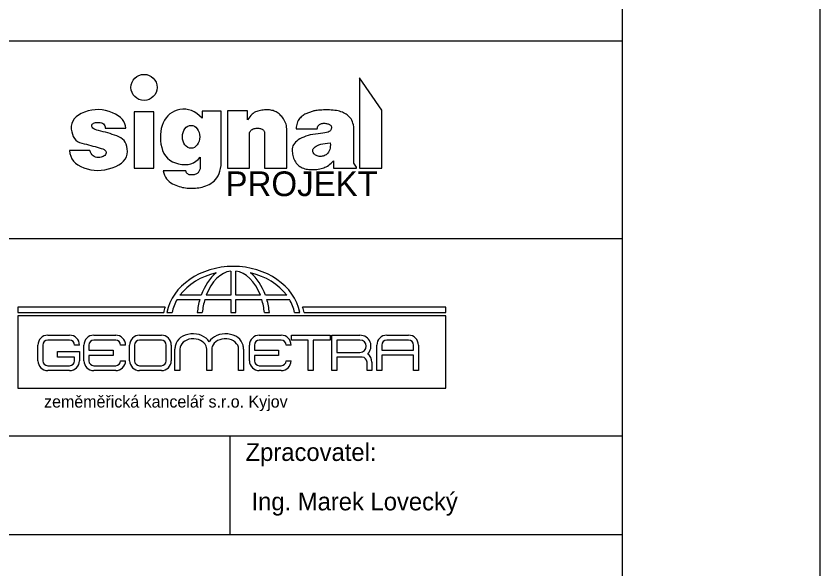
# Model space of a CAD drawing. Extents: x -558358 to -557517, y -1073786 to -1073189.
# Drawn here: x -557597.9 to -557516.5, y -1073685.5 to -1073629.6 of the extents above; entities that cross this region are included whole.
import ezdxf

# ---------------------------------------------------------------- set-up
doc = ezdxf.new("R2010")
doc.units = 0
for name, color, linetype in [('ROZPISKA', 7, 'Continuous'), ('Rozpiska_pole_1', 7, 'Continuous'), ('Rozpiska_pole_6', 7, 'Continuous'), ('Vrstva 1', 7, 'Continuous'), ('ZZZ - Razítko', 7, 'Continuous')]:
    doc.layers.add(name, color=color, linetype=linetype)

msp = doc.modelspace()

# ---------------------------------------------------------------- linework, layer by layer
at = {"layer": 'ROZPISKA'}
for points in [[(-557560.869, -1073644.967), (-557560.869, -1073639.127), (-557563.109, -1073635.847), (-557563.109, -1073644.967), (-557560.869, -1073644.967)], [(-557589.598, -1073645.202), (-557589.236, -1073645.186), (-557588.869, -1073645.138), (-557588.498, -1073645.059), (-557588.122, -1073644.948), (-557587.768, -1073644.812), (-557587.46, -1073644.656), (-557587.199, -1073644.48), (-557586.985, -1073644.284), (-557586.817, -1073644.068), (-557586.697, -1073643.832), (-557586.623, -1073643.576), (-557586.597, -1073643.301), (-557586.607, -1073643.027), (-557586.646, -1073642.778), (-557586.712, -1073642.554), (-557586.806, -1073642.355), (-557586.927, -1073642.18), (-557587.076, -1073642.03), (-557587.253, -1073641.904), (-557587.458, -1073641.804), (-557587.677, -1073641.718), (-557587.899, -1073641.636), (-557588.123, -1073641.558), (-557588.35, -1073641.486), (-557588.579, -1073641.417), (-557588.81, -1073641.353), (-557589.043, -1073641.293), (-557589.279, -1073641.238), (-557589.501, -1073641.183), (-557589.692, -1073641.124), (-557589.852, -1073641.061), (-557589.983, -1073640.994), (-557590.083, -1073640.922), (-557590.152, -1073640.847), (-557590.191, -1073640.768), (-557590.2, -1073640.685), (-557590.183, -1073640.605), (-557590.147, -1073640.537), (-557590.091, -1073640.479), (-557590.015, -1073640.431), (-557589.919, -1073640.395), (-557589.803, -1073640.37), (-557589.668, -1073640.355), (-557589.512, -1073640.351), (-557589.357, -1073640.362), (-557589.222, -1073640.391), (-557589.107, -1073640.439), (-557589.012, -1073640.504), (-557588.937, -1073640.588), (-557588.883, -1073640.69), (-557588.848, -1073640.811), (-557588.834, -1073640.949), (-557586.755, -1073640.949), (-557586.774, -1073640.708), (-557586.836, -1073640.478), (-557586.941, -1073640.261), (-557587.089, -1073640.057), (-557587.28, -1073639.865), (-557587.514, -1073639.686), (-557587.79, -1073639.52), (-557588.11, -1073639.367), (-557588.452, -1073639.237), (-557588.797, -1073639.143), (-557589.145, -1073639.083), (-557589.495, -1073639.058), (-557589.848, -1073639.068), (-557590.203, -1073639.113), (-557590.562, -1073639.193), (-557590.922, -1073639.307), (-557591.26, -1073639.45), (-557591.55, -1073639.612), (-557591.79, -1073639.796), (-557591.983, -1073640), (-557592.126, -1073640.224), (-557592.221, -1073640.469), (-557592.267, -1073640.734), (-557592.265, -1073641.02), (-557592.225, -1073641.302), (-557592.159, -1073641.554), (-557592.067, -1073641.776), (-557591.948, -1073641.969), (-557591.804, -1073642.132), (-557591.633, -1073642.266), (-557591.436, -1073642.37), (-557591.212, -1073642.445), (-557590.977, -1073642.505), (-557590.746, -1073642.565), (-557590.519, -1073642.624), (-557590.295, -1073642.683), (-557590.074, -1073642.741), (-557589.858, -1073642.8), (-557589.645, -1073642.858), (-557589.435, -1073642.916), (-557589.243, -1073642.976), (-557589.081, -1073643.04), (-557588.951, -1073643.109), (-557588.851, -1073643.182), (-557588.783, -1073643.26), (-557588.745, -1073643.343), (-557588.738, -1073643.429), (-557588.762, -1073643.521), (-557588.808, -1073643.609), (-557588.869, -1073643.685), (-557588.945, -1073643.75), (-557589.035, -1073643.803), (-557589.139, -1073643.844), (-557589.257, -1073643.874), (-557589.39, -1073643.893), (-557589.537, -1073643.899), (-557589.686, -1073643.889), (-557589.822, -1073643.856), (-557589.945, -1073643.8), (-557590.056, -1073643.722), (-557590.155, -1073643.62), (-557590.242, -1073643.497), (-557590.316, -1073643.35), (-557590.377, -1073643.182), (-557592.458, -1073643.182), (-557592.414, -1073643.488), (-557592.33, -1073643.771), (-557592.207, -1073644.028), (-557592.045, -1073644.262), (-557591.842, -1073644.472), (-557591.601, -1073644.657), (-557591.319, -1073644.818), (-557590.998, -1073644.954), (-557590.655, -1073645.063), (-557590.307, -1073645.141), (-557589.955, -1073645.187), (-557589.598, -1073645.202)], [(-557583.909, -1073644.967), (-557583.909, -1073639.287), (-557585.909, -1073639.287), (-557585.909, -1073644.967), (-557583.909, -1073644.967)], [(-557580.05, -1073647.009), (-557579.881, -1073647.006), (-557579.711, -1073646.997), (-557579.539, -1073646.984), (-557579.366, -1073646.965), (-557579.192, -1073646.939), (-557579.018, -1073646.9), (-557578.844, -1073646.848), (-557578.67, -1073646.785), (-557578.497, -1073646.71), (-557578.324, -1073646.622), (-557578.152, -1073646.522), (-557577.98, -1073646.41), (-557577.815, -1073646.281), (-557577.667, -1073646.128), (-557577.534, -1073645.952), (-557577.418, -1073645.753), (-557577.317, -1073645.531), (-557577.232, -1073645.286), (-557577.163, -1073645.018), (-557577.109, -1073644.727), (-557577.109, -1073639.207), (-557579.029, -1073639.207), (-557579.029, -1073639.927), (-557579.295, -1073639.673), (-557579.566, -1073639.46), (-557579.84, -1073639.288), (-557580.119, -1073639.157), (-557580.402, -1073639.067), (-557580.69, -1073639.018), (-557580.981, -1073639.01), (-557581.277, -1073639.044), (-557581.564, -1073639.112), (-557581.83, -1073639.209), (-557582.073, -1073639.334), (-557582.295, -1073639.488), (-557582.495, -1073639.67), (-557582.673, -1073639.881), (-557582.83, -1073640.121), (-557582.965, -1073640.388), (-557583.075, -1073640.674), (-557583.16, -1073640.967), (-557583.219, -1073641.267), (-557583.252, -1073641.575), (-557583.259, -1073641.889), (-557583.24, -1073642.211), (-557583.196, -1073642.54), (-557583.125, -1073642.876), (-557583.025, -1073643.199), (-557582.892, -1073643.49), (-557582.727, -1073643.748), (-557582.529, -1073643.974), (-557582.298, -1073644.166), (-557582.035, -1073644.326), (-557581.738, -1073644.454), (-557581.41, -1073644.548), (-557581.073, -1073644.606), (-557580.755, -1073644.624), (-557580.454, -1073644.6), (-557580.171, -1073644.536), (-557579.906, -1073644.432), (-557579.659, -1073644.286), (-557579.429, -1073644.1), (-557579.217, -1073643.873), (-557579.217, -1073644.95), (-557579.236, -1073645.037), (-557579.259, -1073645.119), (-557579.286, -1073645.195), (-557579.319, -1073645.265), (-557579.355, -1073645.33), (-557579.396, -1073645.388), (-557579.442, -1073645.441), (-557579.491, -1073645.489), (-557579.547, -1073645.53), (-557579.61, -1073645.567), (-557579.68, -1073645.598), (-557579.757, -1073645.623), (-557579.841, -1073645.643), (-557579.932, -1073645.658), (-557580.03, -1073645.667), (-557580.135, -1073645.671), (-557580.239, -1073645.666), (-557580.332, -1073645.647), (-557580.415, -1073645.616), (-557580.488, -1073645.571), (-557580.551, -1073645.512), (-557580.604, -1073645.441), (-557580.646, -1073645.356), (-557580.678, -1073645.258), (-557582.986, -1073645.258), (-557582.916, -1073645.485), (-557582.833, -1073645.694), (-557582.736, -1073645.884), (-557582.625, -1073646.056), (-557582.501, -1073646.208), (-557582.362, -1073646.342), (-557582.21, -1073646.457), (-557582.044, -1073646.554), (-557581.872, -1073646.637), (-557581.701, -1073646.711), (-557581.532, -1073646.776), (-557581.364, -1073646.833), (-557581.198, -1073646.882), (-557581.033, -1073646.922), (-557580.87, -1073646.953), (-557580.708, -1073646.975), (-557580.546, -1073646.991), (-557580.382, -1073647.002), (-557580.217, -1073647.008), (-557580.05, -1073647.009)], [(-557570.469, -1073644.967), (-557570.469, -1073641.167), (-557570.472, -1073640.997), (-557570.486, -1073640.834), (-557570.511, -1073640.677), (-557570.547, -1073640.527), (-557570.593, -1073640.384), (-557570.65, -1073640.247), (-557570.718, -1073640.117), (-557570.796, -1073639.993), (-557570.881, -1073639.877), (-557570.968, -1073639.769), (-557571.057, -1073639.669), (-557571.148, -1073639.577), (-557571.241, -1073639.494), (-557571.336, -1073639.418), (-557571.433, -1073639.351), (-557571.532, -1073639.293), (-557571.635, -1073639.241), (-557571.741, -1073639.197), (-557571.852, -1073639.16), (-557571.967, -1073639.129), (-557572.086, -1073639.106), (-557572.21, -1073639.089), (-557572.338, -1073639.079), (-557572.47, -1073639.077), (-557572.604, -1073639.08), (-557572.736, -1073639.088), (-557572.868, -1073639.101), (-557572.998, -1073639.119), (-557573.127, -1073639.142), (-557573.255, -1073639.17), (-557573.381, -1073639.202), (-557573.507, -1073639.24), (-557573.63, -1073639.288), (-557573.752, -1073639.353), (-557573.871, -1073639.434), (-557573.987, -1073639.532), (-557574.101, -1073639.646), (-557574.213, -1073639.777), (-557574.322, -1073639.924), (-557574.429, -1073640.087), (-557574.429, -1073639.167), (-557576.469, -1073639.167), (-557576.469, -1073644.967), (-557574.229, -1073644.967), (-557574.229, -1073641.407), (-557574.195, -1073641.316), (-557574.15, -1073641.235), (-557574.096, -1073641.164), (-557574.032, -1073641.103), (-557573.958, -1073641.052), (-557573.874, -1073641.011), (-557573.78, -1073640.98), (-557573.676, -1073640.959), (-557573.57, -1073640.946), (-557573.469, -1073640.939), (-557573.374, -1073640.938), (-557573.283, -1073640.944), (-557573.198, -1073640.955), (-557573.119, -1073640.973), (-557573.044, -1073640.996), (-557572.975, -1073641.026), (-557572.913, -1073641.061), (-557572.859, -1073641.099), (-557572.813, -1073641.141), (-557572.776, -1073641.187), (-557572.747, -1073641.237), (-557572.726, -1073641.29), (-557572.713, -1073641.347), (-557572.709, -1073641.407), (-557572.709, -1073644.967), (-557570.469, -1073644.967)], [(-557567.906, -1073645.131), (-557567.745, -1073645.128), (-557567.587, -1073645.12), (-557567.434, -1073645.105), (-557567.285, -1073645.085), (-557567.14, -1073645.06), (-557567, -1073645.028), (-557566.864, -1073644.991), (-557566.732, -1073644.948), (-557566.604, -1073644.896), (-557566.477, -1073644.835), (-557566.351, -1073644.763), (-557566.228, -1073644.681), (-557566.106, -1073644.588), (-557565.985, -1073644.485), (-557565.866, -1073644.371), (-557565.749, -1073644.247), (-557565.749, -1073644.967), (-557563.429, -1073644.967), (-557563.429, -1073644.887), (-557563.669, -1073644.487), (-557563.669, -1073641.007), (-557563.696, -1073640.803), (-557563.731, -1073640.612), (-557563.777, -1073640.437), (-557563.832, -1073640.276), (-557563.896, -1073640.129), (-557563.97, -1073639.997), (-557564.054, -1073639.879), (-557564.147, -1073639.775), (-557564.248, -1073639.683), (-557564.355, -1073639.597), (-557564.469, -1073639.518), (-557564.589, -1073639.446), (-557564.715, -1073639.381), (-557564.847, -1073639.323), (-557564.986, -1073639.272), (-557565.131, -1073639.228), (-557565.283, -1073639.19), (-557565.442, -1073639.158), (-557565.608, -1073639.131), (-557565.782, -1073639.11), (-557565.962, -1073639.095), (-557566.15, -1073639.086), (-557566.346, -1073639.082), (-557566.548, -1073639.085), (-557566.747, -1073639.091), (-557566.931, -1073639.099), (-557567.1, -1073639.109), (-557567.254, -1073639.122), (-557567.394, -1073639.137), (-557567.519, -1073639.154), (-557567.63, -1073639.174), (-557567.725, -1073639.195), (-557567.814, -1073639.219), (-557567.903, -1073639.245), (-557567.993, -1073639.272), (-557568.084, -1073639.302), (-557568.175, -1073639.333), (-557568.268, -1073639.367), (-557568.36, -1073639.402), (-557568.454, -1073639.44), (-557568.547, -1073639.481), (-557568.639, -1073639.53), (-557568.73, -1073639.585), (-557568.821, -1073639.647), (-557568.91, -1073639.716), (-557568.998, -1073639.792), (-557569.085, -1073639.875), (-557569.171, -1073639.964), (-557569.251, -1073640.062), (-557569.321, -1073640.169), (-557569.379, -1073640.285), (-557569.427, -1073640.411), (-557569.464, -1073640.546), (-557569.49, -1073640.69), (-557569.505, -1073640.844), (-557569.509, -1073641.007), (-557567.389, -1073641.007), (-557567.374, -1073640.911), (-557567.35, -1073640.824), (-557567.317, -1073640.746), (-557567.275, -1073640.677), (-557567.225, -1073640.617), (-557567.167, -1073640.567), (-557567.099, -1073640.525), (-557567.023, -1073640.493), (-557566.943, -1073640.469), (-557566.862, -1073640.451), (-557566.78, -1073640.439), (-557566.698, -1073640.435), (-557566.616, -1073640.436), (-557566.532, -1073640.445), (-557566.449, -1073640.459), (-557566.364, -1073640.481), (-557566.284, -1073640.506), (-557566.213, -1073640.534), (-557566.15, -1073640.564), (-557566.097, -1073640.596), (-557566.051, -1073640.63), (-557566.015, -1073640.666), (-557565.987, -1073640.705), (-557565.969, -1073640.745), (-557565.957, -1073640.788), (-557565.952, -1073640.834), (-557565.953, -1073640.883), (-557565.961, -1073640.934), (-557565.974, -1073640.988), (-557565.994, -1073641.045), (-557566.021, -1073641.105), (-557566.053, -1073641.168), (-557566.104, -1073641.229), (-557566.185, -1073641.285), (-557566.296, -1073641.335), (-557566.438, -1073641.381), (-557566.61, -1073641.421), (-557566.812, -1073641.456), (-557567.045, -1073641.485), (-557567.308, -1073641.509), (-557567.58, -1073641.536), (-557567.839, -1073641.573), (-557568.086, -1073641.621), (-557568.321, -1073641.68), (-557568.544, -1073641.749), (-557568.755, -1073641.828), (-557568.953, -1073641.918), (-557569.139, -1073642.019), (-557569.308, -1073642.127), (-557569.456, -1073642.24), (-557569.584, -1073642.357), (-557569.69, -1073642.479), (-557569.776, -1073642.605), (-557569.841, -1073642.735), (-557569.885, -1073642.871), (-557569.908, -1073643.01), (-557569.916, -1073643.152), (-557569.915, -1073643.292), (-557569.905, -1073643.431), (-557569.886, -1073643.569), (-557569.858, -1073643.705), (-557569.821, -1073643.841), (-557569.775, -1073643.975), (-557569.72, -1073644.108), (-557569.657, -1073644.237), (-557569.587, -1073644.356), (-557569.51, -1073644.466), (-557569.426, -1073644.568), (-557569.335, -1073644.66), (-557569.238, -1073644.744), (-557569.133, -1073644.819), (-557569.022, -1073644.885), (-557568.904, -1073644.943), (-557568.78, -1073644.993), (-557568.65, -1073645.035), (-557568.513, -1073645.07), (-557568.371, -1073645.097), (-557568.222, -1073645.116), (-557568.067, -1073645.127), (-557567.906, -1073645.131)], [(-557567.191, -1073643.787), (-557567.294, -1073643.766), (-557567.388, -1073643.738), (-557567.475, -1073643.702), (-557567.554, -1073643.659), (-557567.625, -1073643.607), (-557567.688, -1073643.548), (-557567.743, -1073643.481), (-557567.789, -1073643.407), (-557567.824, -1073643.329), (-557567.842, -1073643.252), (-557567.843, -1073643.176), (-557567.827, -1073643.101), (-557567.795, -1073643.027), (-557567.746, -1073642.954), (-557567.68, -1073642.881), (-557567.597, -1073642.81), (-557567.494, -1073642.742), (-557567.365, -1073642.679), (-557567.211, -1073642.621), (-557567.032, -1073642.568), (-557566.828, -1073642.521), (-557566.599, -1073642.479), (-557566.344, -1073642.443), (-557566.064, -1073642.412), (-557566.06, -1073642.61), (-557566.069, -1073642.792), (-557566.091, -1073642.958), (-557566.125, -1073643.108), (-557566.173, -1073643.241), (-557566.233, -1073643.359), (-557566.306, -1073643.46), (-557566.393, -1073643.545), (-557566.486, -1073643.617), (-557566.582, -1073643.676), (-557566.679, -1073643.724), (-557566.778, -1073643.76), (-557566.878, -1073643.784), (-557566.981, -1073643.797), (-557567.085, -1073643.798), (-557567.191, -1073643.787)]]:
    msp.add_lwpolyline(points, dxfattribs=at)
msp.add_circle((-557584.909, -1073636.807), 1.32, dxfattribs=at)
msp.add_ellipse((-557580.149, -1073641.807), major_axis=(0, 1.16), ratio=0.758621, dxfattribs=at)
at = {"layer": 'Rozpiska_pole_1'}
msp.add_lwpolyline([(-557706.534, -1073507.088), (-557536.534, -1073507.088), (-557536.534, -1073767.088), (-557706.534, -1073767.088)], close=True, dxfattribs=at)
at = {"layer": 'Rozpiska_pole_6'}
for p, q in [((-557706.534, -1073652.088), (-557536.534, -1073652.088)), ((-557706.534, -1073672.088), (-557536.534, -1073672.088)), ((-557576.184, -1073682.088), (-557576.184, -1073672.088))]:
    msp.add_line(p, q, dxfattribs=at)
msp.add_lwpolyline([(-557706.534, -1073632.088), (-557536.534, -1073632.088), (-557536.534, -1073682.088), (-557706.534, -1073682.088)], close=True, dxfattribs=at)
at = {"layer": 'Vrstva 1'}
msp.add_line((-557516.534, -1073190.088), (-557516.534, -1073784.088), dxfattribs=at)
at = {"layer": 'ZZZ - Razítko'}
for p, q in [((-557576.139, -1073655.401), (-557576.139, -1073657.847)), ((-557575.632, -1073657.847), (-557575.632, -1073655.399)), ((-557579.132, -1073657.847), (-557581.277, -1073657.847)), ((-557576.139, -1073657.847), (-557578.615, -1073657.847)), ((-557573.137, -1073657.847), (-557575.632, -1073657.847)), ((-557570.475, -1073657.847), (-557572.62, -1073657.847)), ((-557581.552, -1073658.258), (-557579.265, -1073658.258)), ((-557578.755, -1073658.258), (-557576.139, -1073658.258)), ((-557576.139, -1073658.258), (-557576.139, -1073659.578)), ((-557575.632, -1073659.578), (-557575.632, -1073658.258)), ((-557575.632, -1073658.258), (-557572.998, -1073658.258)), ((-557572.488, -1073658.258), (-557570.2, -1073658.258)), ((-557582.783, -1073659.047), (-557597.663, -1073659.047)), ((-557597.663, -1073659.047), (-557597.663, -1073659.578)), ((-557597.663, -1073659.578), (-557582.921, -1073659.578)), ((-557582.595, -1073659.578), (-557582.078, -1073659.578)), ((-557579.522, -1073659.578), (-557579.022, -1073659.578)), ((-557576.139, -1073659.578), (-557575.632, -1073659.578)), ((-557572.731, -1073659.578), (-557572.23, -1073659.578)), ((-557569.674, -1073659.578), (-557569.157, -1073659.578)), ((-557554.385, -1073659.047), (-557568.863, -1073659.047)), ((-557568.725, -1073659.578), (-557554.385, -1073659.578)), ((-557554.385, -1073659.578), (-557554.385, -1073659.047)), ((-557554.387, -1073659.923), (-557597.67, -1073659.923)), ((-557597.67, -1073659.923), (-557597.67, -1073667.261)), ((-557554.387, -1073667.261), (-557554.387, -1073659.923)), ((-557594.645, -1073661.889), (-557592.434, -1073661.889)), ((-557589.989, -1073661.889), (-557587.778, -1073661.889)), ((-557585.365, -1073661.889), (-557583.154, -1073661.889)), ((-557573.246, -1073661.889), (-557571.036, -1073661.889)), ((-557565.909, -1073661.889), (-557563.064, -1073661.889)), ((-557560.361, -1073661.889), (-557558.15, -1073661.889)), ((-557595.643, -1073664.473), (-557595.643, -1073662.887)), ((-557595.144, -1073662.887), (-557595.144, -1073664.473)), ((-557592.434, -1073662.387), (-557594.645, -1073662.387)), ((-557591.437, -1073662.887), (-557591.935, -1073662.887)), ((-557590.986, -1073664.473), (-557590.986, -1073662.887)), ((-557590.488, -1073662.887), (-557590.488, -1073663.397)), ((-557587.778, -1073662.387), (-557589.989, -1073662.387)), ((-557586.78, -1073662.887), (-557587.279, -1073662.887)), ((-557586.363, -1073664.473), (-557586.363, -1073662.887)), ((-557585.864, -1073662.887), (-557585.864, -1073664.473)), ((-557583.154, -1073662.387), (-557585.365, -1073662.387)), ((-557582.655, -1073664.473), (-557582.655, -1073662.887)), ((-557582.156, -1073662.887), (-557582.156, -1073664.473)), ((-557574.244, -1073664.473), (-557574.244, -1073662.887)), ((-557573.745, -1073662.887), (-557573.745, -1073663.397)), ((-557571.036, -1073662.387), (-557573.246, -1073662.387)), ((-557570.038, -1073662.887), (-557570.536, -1073662.887)), ((-557568.303, -1073665.471), (-557568.303, -1073662.375)), ((-557567.8, -1073662.375), (-557567.8, -1073665.471)), ((-557563.064, -1073662.378), (-557565.405, -1073662.378)), ((-557565.405, -1073662.378), (-557565.405, -1073663.627)), ((-557561.359, -1073665.471), (-557561.359, -1073662.887)), ((-557560.86, -1073662.887), (-557560.86, -1073663.395)), ((-557558.15, -1073662.387), (-557560.361, -1073662.387)), ((-557557.651, -1073663.395), (-557557.651, -1073662.887)), ((-557557.152, -1073662.887), (-557557.152, -1073665.471)), ((-557593.67, -1073664.095), (-557593.67, -1073663.55)), ((-557593.67, -1073663.55), (-557591.437, -1073663.55)), ((-557591.437, -1073663.55), (-557591.437, -1073664.473)), ((-557590.488, -1073663.397), (-557588.045, -1073663.397)), ((-557588.045, -1073663.397), (-557588.045, -1073663.942)), ((-557581.784, -1073665.471), (-557581.784, -1073663.286)), ((-557581.283, -1073663.286), (-557581.283, -1073665.471)), ((-557578.564, -1073665.471), (-557578.564, -1073663.286)), ((-557578.063, -1073663.286), (-557578.063, -1073665.471)), ((-557575.345, -1073665.471), (-557575.345, -1073663.286)), ((-557574.844, -1073663.286), (-557574.844, -1073665.471)), ((-557573.745, -1073663.397), (-557571.302, -1073663.397)), ((-557571.302, -1073663.397), (-557571.302, -1073663.942)), ((-557565.405, -1073663.627), (-557563.064, -1073663.627)), ((-557560.86, -1073663.395), (-557557.651, -1073663.395)), ((-557591.935, -1073664.095), (-557593.67, -1073664.095)), ((-557591.935, -1073664.473), (-557591.935, -1073664.095)), ((-557588.045, -1073663.942), (-557590.488, -1073663.942)), ((-557590.488, -1073663.942), (-557590.488, -1073664.473)), ((-557587.279, -1073664.473), (-557586.78, -1073664.473)), ((-557571.302, -1073663.942), (-557573.745, -1073663.942)), ((-557573.745, -1073663.942), (-557573.745, -1073664.473)), ((-557570.536, -1073664.473), (-557570.038, -1073664.473)), ((-557563.064, -1073664.116), (-557565.405, -1073664.116)), ((-557562.85, -1073664.12), (-557563.064, -1073664.116)), ((-557562.351, -1073665.471), (-557562.351, -1073664.619)), ((-557561.853, -1073664.619), (-557561.853, -1073665.471)), ((-557557.651, -1073663.899), (-557560.86, -1073663.899)), ((-557560.86, -1073663.899), (-557560.86, -1073665.471)), ((-557557.651, -1073665.471), (-557557.651, -1073663.899)), ((-557594.645, -1073664.972), (-557592.434, -1073664.972)), ((-557592.434, -1073665.471), (-557594.645, -1073665.471)), ((-557589.989, -1073664.972), (-557587.778, -1073664.972)), ((-557587.778, -1073665.471), (-557589.989, -1073665.471)), ((-557585.365, -1073664.972), (-557583.154, -1073664.972)), ((-557583.154, -1073665.471), (-557585.365, -1073665.471)), ((-557581.283, -1073665.471), (-557581.784, -1073665.471)), ((-557578.063, -1073665.471), (-557578.564, -1073665.471)), ((-557574.844, -1073665.471), (-557575.345, -1073665.471)), ((-557573.246, -1073664.972), (-557571.036, -1073664.972)), ((-557571.036, -1073665.471), (-557573.246, -1073665.471)), ((-557567.8, -1073665.471), (-557568.303, -1073665.471)), ((-557561.853, -1073665.471), (-557562.351, -1073665.471)), ((-557560.86, -1073665.471), (-557561.359, -1073665.471)), ((-557557.152, -1073665.471), (-557557.651, -1073665.471)), ((-557597.67, -1073667.261), (-557554.387, -1073667.261))]:
    msp.add_line(p, q, dxfattribs=at)
for points in [[(-557568.303, -1073662.375), (-557570.001, -1073662.375), (-557570.001, -1073661.889), (-557566.087, -1073661.889)], [(-557566.087, -1073661.889), (-557566.087, -1073662.375), (-557567.8, -1073662.375)], [(-557565.405, -1073664.116), (-557565.405, -1073665.471), (-557565.909, -1073665.471), (-557565.909, -1073661.889)]]:
    msp.add_lwpolyline(points, dxfattribs=at)
for centre, radius, start, end in [((-557594.645, -1073662.887), 0.998, 90, 180), ((-557592.434, -1073662.887), 0.998, 360, 90), ((-557589.989, -1073662.887), 0.998, 90, 180), ((-557587.778, -1073662.887), 0.998, 360, 90), ((-557585.365, -1073662.887), 0.998, 90, 180), ((-557583.154, -1073662.887), 0.998, 360, 90), ((-557573.246, -1073662.887), 0.998, 90, 180), ((-557571.036, -1073662.887), 0.998, 360, 90), ((-557563.064, -1073663.003), 1.114, 314.45734, 90), ((-557560.361, -1073662.887), 0.998, 90, 180), ((-557558.15, -1073662.887), 0.998, 360, 90), ((-557594.645, -1073662.887), 0.499, 90, 180), ((-557592.434, -1073662.887), 0.499, 0, 90), ((-557589.989, -1073662.887), 0.499, 90, 180), ((-557587.778, -1073662.887), 0.499, 0, 90), ((-557585.365, -1073662.887), 0.499, 90, 180), ((-557583.154, -1073662.887), 0.499, 0, 90), ((-557579.846, -1073663.336), 1.938, 166.96576, 178.52091), ((-557579.518, -1073663.35), 0.957, 3.86486, 22.41569), ((-557576.831, -1073663.408), 1.238, 162.61388, 174.3506), ((-557576.782, -1073663.336), 1.938, 1.47909, 13.03424), ((-557573.246, -1073662.887), 0.499, 90, 180), ((-557571.036, -1073662.887), 0.499, 0, 90), ((-557563.064, -1073663.003), 0.625, 270, 90), ((-557560.361, -1073662.887), 0.499, 90, 180), ((-557558.15, -1073662.887), 0.499, 0, 90), ((-557562.85, -1073664.619), 0.998, 360, 55.44734), ((-557594.645, -1073664.473), 0.998, 180, 270), ((-557594.645, -1073664.473), 0.499, 180, 270), ((-557592.434, -1073664.473), 0.998, 270, 0), ((-557592.434, -1073664.473), 0.499, 270, 0), ((-557589.989, -1073664.473), 0.998, 180, 270), ((-557589.989, -1073664.473), 0.499, 180, 270), ((-557587.778, -1073664.473), 0.998, 270, 0), ((-557587.778, -1073664.473), 0.499, 270, 0), ((-557585.365, -1073664.473), 0.998, 180, 270), ((-557585.365, -1073664.473), 0.499, 180, 270), ((-557583.154, -1073664.473), 0.998, 270, 0), ((-557583.154, -1073664.473), 0.499, 270, 0), ((-557573.246, -1073664.473), 0.998, 180, 270), ((-557573.246, -1073664.473), 0.499, 180, 270), ((-557571.036, -1073664.473), 0.998, 270, 0), ((-557571.036, -1073664.473), 0.499, 270, 0), ((-557562.85, -1073664.619), 0.499, 0, 90)]:
    msp.add_arc(centre, radius, start, end, dxfattribs=at)
for centre, major_axis, ratio, start_param, end_param in [((-557575.876, -1073660.451), (-6.804, 0), 0.811768, 3.300239, 6.124539), ((-557575.876, -1073660.451), (-6.296, 0), 0.804826, 4.992897, 5.743383), ((-557575.876, -1073660.451), (0, 5.524), 0.668443, 0.491666, 1.079789), ((-557575.876, -1073660.451), (0, 5.067), 0.630136, 0.08224, 1.030995), ((-557575.876, -1073660.451), (0, 5.067), 0.630136, 5.252191, 6.206521), ((-557575.876, -1073660.451), (0, 5.524), 0.668443, 5.203397, 5.79152), ((-557575.876, -1073660.451), (-6.296, 0), 0.804826, 3.681394, 4.431881), ((-557575.876, -1073660.451), (-6.296, 0), 0.804826, 5.835664, 6.110118), ((-557575.876, -1073660.451), (0, 5.524), 0.668443, 1.16256, 1.41215), ((-557575.876, -1073660.451), (0, 5.067), 0.630136, 1.123275, 1.397729), ((-557575.876, -1073660.451), (0, 5.067), 0.630136, 4.885456, 5.159911), ((-557575.876, -1073660.451), (0, 5.524), 0.668443, 4.871035, 5.120625), ((-557575.876, -1073660.451), (-6.296, 0), 0.804826, 3.31466, 3.589114), ((-557576.202, -1073660.451), (-6.804, 0), 0.811768, 6.026233, 6.124539), ((-557575.444, -1073660.451), (-6.804, 0), 0.811768, 3.300239, 3.398545), ((-557579.955, -1073663.13), (1.805, 0), 0.766187, 0.429647, 2.97338), ((-557579.93, -1073663.286), (1.354, 0), 0.766187, 0.29376, 3.141593), ((-557576.673, -1073663.13), (-1.805, 0), 0.766187, 3.309805, 5.853538), ((-557576.698, -1073663.286), (-1.354, 0), 0.766187, 3.141593, 6.041607)]:
    msp.add_ellipse(centre, major_axis=major_axis, ratio=ratio, start_param=start_param, end_param=end_param, dxfattribs=at)

# ---------------------------------------------------------------- texts
at = {"layer": 'ROZPISKA'}
msp.add_text('PROJEKT', height=2.5, dxfattribs=at).set_placement((-557576.669, -1073647.81))
at = {"layer": 'Rozpiska_pole_6'}
for s, p in [('Zpracovatel:', (-557574.638, -1073674.615)), ('Ing. Marek Lovecký', (-557574.037, -1073679.615))]:
    msp.add_text(s, height=1.8, dxfattribs=at).set_placement(p)
at = {"layer": 'ZZZ - Razítko'}
msp.add_text('zeměměřická kancelář s.r.o. Kyjov', height=1.20984, dxfattribs=at).set_placement((-557595.018, -1073669.21))

doc.saveas('drawing.dxf')
